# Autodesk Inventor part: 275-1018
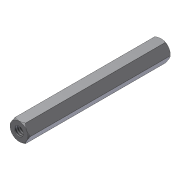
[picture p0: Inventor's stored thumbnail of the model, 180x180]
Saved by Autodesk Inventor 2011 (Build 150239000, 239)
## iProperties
Company: Autodesk Inc.
Created: 2005-07
Part Number: 275-1018
Document SubType Name: Modeling
Designer: Autodesk Inc.
Density: 1 g/cm^3
Catalog Web Link: http://www.vexrobotics.com/products/accessories/structure/standoffs-8-32.html
Description: A standoff is used in mechanics and electronics to separate two parts from one another. All VEX Standoffs have 8-32 threads.
Vendor: Innovation First, Inc.
Author: Autodesk Inc.
Title: VEX Robotics Kit of Parts
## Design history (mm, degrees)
sketch "Sketch1"
  geometry: L1 (1.955, -3.175)-(-1.711, -3.175); L2 (-1.711, -3.175)-(-3.544, 0); L3 (-3.544, 0)-(-1.711, 3.175); L4 (-1.711, 3.175)-(1.955, 3.175); L5 (1.955, 3.175)-(3.788, 0); L6 (3.788, 0)-(1.955, -3.175); 1 further point
  constraints: 12 end point, 1 horizontal, 11 other
  dimensions: "d0" = 6.35 distance between parallel lines of L1 L4
extrude "Extrusion1" new body sketch "Sketch1" distance "d1" = 50.8; taper "d2" = 0 deg
workplane "Work Plane1"
sketch "Sketch3"
  geometry: L1 (-1.325, 0)-(4.974, 0); L2 (5.482, -0.508)-(5.482, -50.292); L3 (4.974, -50.8)-(-1.325, -50.8); L4 (-1.833, -50.292)-(-1.833, -0.508); L5 (-1.833, -0.508)-(-1.325, 0); L6 (4.974, 0)-(5.482, -0.508); L7 (-1.325, -50.8)-(-1.833, -50.292); L8 (5.482, -50.292)-(4.974, -50.8); L9 (-1.833, 0)-(-1.833, -50.8) reference; L10 (3.666, 0)-(5.499, 0) reference; L11 (1.825, 0)-(1.825, -50.8); 4 further points
  constraints: 18 end point, 8 point on line, 2 midpoint, 2 parallel, 1 horizontal, 1 perpendicular
  dimensions: "d5" = 0.508 distance of L4.end point (-1.833, 0); "d6" = 0.508 distance of L1.start point (-1.833, 0) (= d5); "d7" = 0.508 distance of L1.end point (5.482, 0) (= d5); "d8" = 0.508 distance of L2.start point (5.482, 0) (= d7); "d9" = 0.508 distance of L3.end point (-1.833, -50.8) (= d5); "d10" = 0.508 distance of L4.start point (-1.833, -50.8) (= d9); "d11" = 0.508 distance of L2.end point (5.482, -50.8) (= d5); "d12" = 0.508 distance of L3.start point (5.482, -50.8) (= d11); "d13" = 7.3152 distance between parallel lines of L2 L4; "d14" = 0 distance between parallel lines of L9 L4; "d15" = 50.8 distance between parallel lines of L1 L3; "d16" = 0 distance between parallel lines of L1 L10
revolve "Revolution1" sketch "Sketch3" stored, may be unused: angle "d17" = 90 deg
sketch "Sketch5"
  geometry: C1 r 3.15 at (0, 0) reference; 1 further point
  constraints: 1 coincident
hole "Hole2" sketch "Sketch5" at (0, 0) diameter "d25" = 3.302; stored, may be unused: countersink angle "d29" = 82 deg, drill point angle "d31" = 118 deg; dims "d26" = 12.7, "d27" = 9.525, "d28" = 6.35, "d30" = 12.7
sketch "Sketch6"
  geometry: C1 r 3.15 at (0, 0) reference; 1 further point
  constraints: 1 coincident
hole "Hole3" sketch "Sketch6" at (0, 0) diameter "d32" = 3.302; stored, may be unused: countersink angle "d36" = 82 deg, drill point angle "d38" = 118 deg; dims "d33" = 12.7, "d34" = 9.525, "d35" = 6.35, "d37" = 12.7
body "Solid1"
other parameters: "d4" = -3.175
